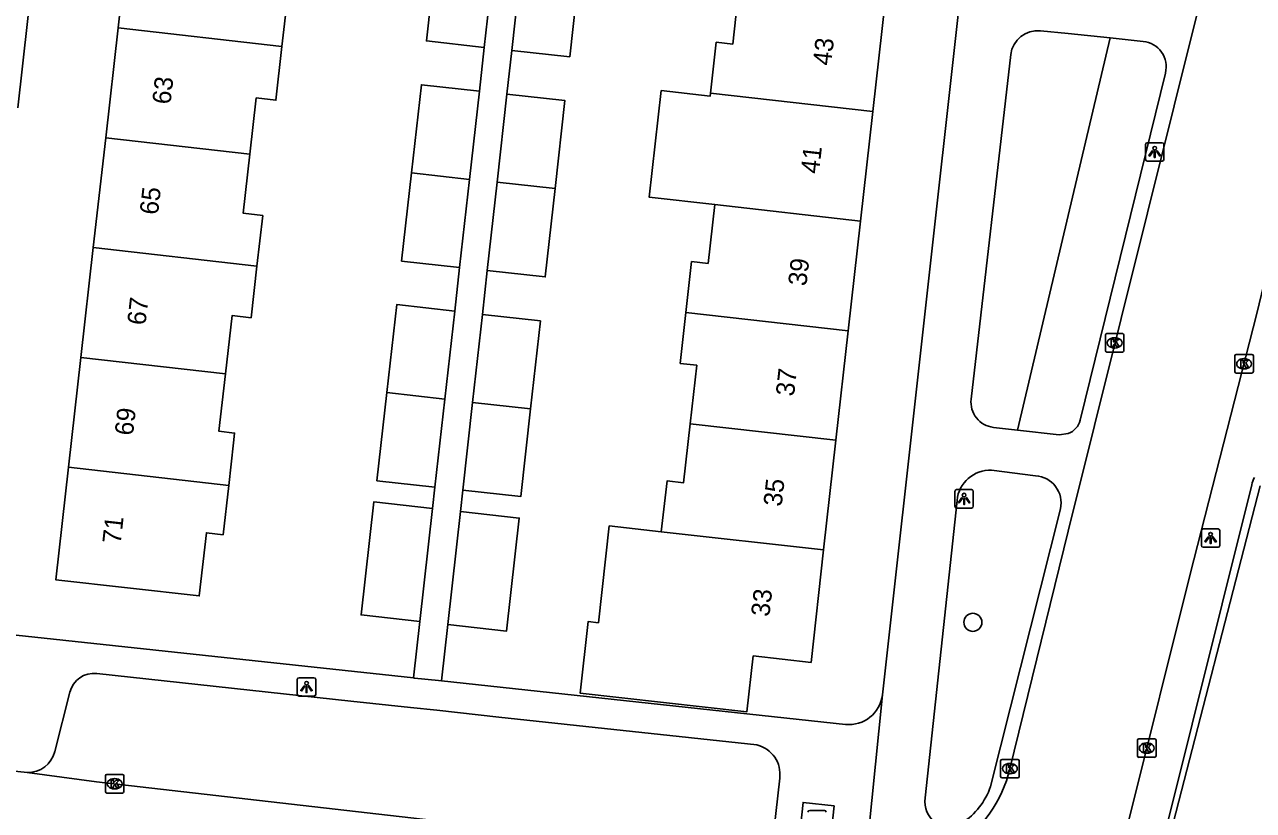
# Model space of a CAD drawing. Extents: x 162026 to 163499, y 387297 to 388169.
# Drawn here: x 162443.5 to 162510, y 387793.2 to 387835.8 of the extents above; entities that cross this region are included whole.
import ezdxf

# ---------------------------------------------------------------- set-up
doc = ezdxf.new("R2010")
doc.units = 0
for name, color, linetype in [('IMGEO_Afval_apart_plaats', 7, 'Continuous'), ('IMGEO_Boom', 7, 'Continuous'), ('IMGEO_Groenvoorziening', 7, 'Continuous'), ('IMGEO_Haag', 7, 'Continuous'), ('IMGEO_Kolk', 7, 'Continuous'), ('IMGEO_Lichtpunt', 7, 'Continuous'), ('IMGEO_Pand', 7, 'Continuous'), ('IMGEO_Pand_nummerreeks', 7, 'Continuous'), ('IMGEO_Rijbaan_lokaal_open', 7, 'Continuous'), ('IMGEO_Voetpad_gesloten', 7, 'Continuous'), ('IMGEO_Voetpad_open', 7, 'Continuous')]:
    doc.layers.add(name, color=color, linetype=linetype)

msp = doc.modelspace()

# ---------------------------------------------------------------- linework, layer by layer
at = {"layer": 'IMGEO_Afval_apart_plaats'}
for p, q in [((162485.995, 387793.2), (162486.785, 387793.2)), ((162486.785, 387793.2), (162485.995, 387793.2))]:
    msp.add_line(p, q, dxfattribs=at)
for centre, start, end in [((162485.995, 387793.1), 90, 180), ((162485.995, 387793.1), 90, 180), ((162486.785, 387793.1), 0, 90), ((162486.785, 387793.1), 360, 90)]:
    msp.add_arc(centre, 0.1, start, end, dxfattribs=at)
at = {"layer": 'IMGEO_Boom'}
msp.add_circle((162494.83, 387803.388), 0.489, dxfattribs=at)
at = {"layer": 'IMGEO_Groenvoorziening'}
msp.add_lwpolyline([(162502.275, 387835.042), (162500, 387825.424), (162497.251, 387813.802)], dxfattribs=at)
at = {"layer": 'IMGEO_Haag'}
msp.add_lwpolyline([(162505.401, 387791.389), (162510.401, 387810.785)], dxfattribs=at)
at = {"layer": 'IMGEO_Kolk'}
for p, q in [((162502.011, 387818.101), (162502.011, 387818.953)), ((162502.086, 387819.027), (162502.938, 387819.027)), ((162502.499, 387818.807), (162502.524, 387818.807)), ((162503.012, 387818.953), (162503.012, 387818.101)), ((162502.938, 387818.027), (162502.086, 387818.027)), ((162502.522, 387818.247), (162502.497, 387818.247)), ((162509.025, 387816.966), (162509.025, 387817.818)), ((162509.1, 387817.892), (162509.952, 387817.892)), ((162510.026, 387817.818), (162510.026, 387816.966)), ((162509.513, 387817.672), (162509.538, 387817.672)), ((162509.952, 387816.892), (162509.1, 387816.892)), ((162509.536, 387817.112), (162509.511, 387817.112)), ((162503.752, 387796.149), (162503.752, 387797.001)), ((162503.827, 387797.075), (162504.679, 387797.075)), ((162504.24, 387796.855), (162504.265, 387796.855)), ((162504.753, 387797.001), (162504.753, 387796.149)), ((162496.336, 387795.036), (162496.336, 387795.888)), ((162496.411, 387795.962), (162497.263, 387795.962)), ((162497.337, 387795.888), (162497.337, 387795.036)), ((162504.679, 387796.075), (162503.827, 387796.075)), ((162504.263, 387796.295), (162504.238, 387796.295)), ((162496.847, 387795.182), (162496.822, 387795.182)), ((162496.824, 387795.742), (162496.849, 387795.742)), ((162447.835, 387794.217), (162447.835, 387795.069)), ((162447.91, 387795.143), (162448.762, 387795.143)), ((162448.323, 387794.923), (162448.348, 387794.923)), ((162448.836, 387795.069), (162448.836, 387794.217)), ((162497.263, 387794.962), (162496.411, 387794.962)), ((162448.762, 387794.143), (162447.91, 387794.143)), ((162448.346, 387794.363), (162448.321, 387794.363))]:
    msp.add_line(p, q, dxfattribs=at)
for points in [[(162502.011, 387818.101), (162502.011, 387818.953)], [(162502.086, 387819.027), (162502.938, 387819.027)], [(162502.332, 387818.727), (162502.455, 387818.727), (162502.455, 387818.576), (162502.585, 387818.727), (162502.749, 387818.727), (162502.603, 387818.576), (162502.756, 387818.327), (162502.604, 387818.327), (162502.519, 387818.491), (162502.455, 387818.424), (162502.455, 387818.327), (162502.332, 387818.327), (162502.332, 387818.727)], [(162503.012, 387818.953), (162503.012, 387818.101)], [(162502.938, 387818.027), (162502.086, 387818.027)], [(162509.025, 387816.966), (162509.025, 387817.818)], [(162509.1, 387817.892), (162509.952, 387817.892)], [(162510.026, 387817.818), (162510.026, 387816.966)], [(162509.346, 387817.592), (162509.469, 387817.592), (162509.469, 387817.441), (162509.599, 387817.592), (162509.763, 387817.592), (162509.617, 387817.441), (162509.77, 387817.192), (162509.618, 387817.192), (162509.533, 387817.356), (162509.469, 387817.289), (162509.469, 387817.192), (162509.346, 387817.192), (162509.346, 387817.592)], [(162509.952, 387816.892), (162509.1, 387816.892)], [(162503.752, 387796.149), (162503.752, 387797.001)], [(162503.827, 387797.075), (162504.679, 387797.075)], [(162504.073, 387796.775), (162504.196, 387796.775), (162504.196, 387796.624), (162504.326, 387796.775), (162504.49, 387796.775), (162504.344, 387796.624), (162504.497, 387796.375), (162504.345, 387796.375), (162504.26, 387796.539), (162504.196, 387796.472), (162504.196, 387796.375), (162504.073, 387796.375), (162504.073, 387796.775)], [(162504.753, 387797.001), (162504.753, 387796.149)], [(162496.336, 387795.036), (162496.336, 387795.888)], [(162496.411, 387795.962), (162497.263, 387795.962)], [(162497.337, 387795.888), (162497.337, 387795.036)], [(162504.679, 387796.075), (162503.827, 387796.075)], [(162496.657, 387795.662), (162496.78, 387795.662), (162496.78, 387795.511), (162496.91, 387795.662), (162497.074, 387795.662), (162496.928, 387795.511), (162497.081, 387795.262), (162496.929, 387795.262), (162496.844, 387795.426), (162496.78, 387795.359), (162496.78, 387795.262), (162496.657, 387795.262), (162496.657, 387795.662)], [(162447.835, 387794.217), (162447.835, 387795.069)], [(162447.91, 387795.143), (162448.762, 387795.143)], [(162448.156, 387794.843), (162448.279, 387794.843), (162448.279, 387794.692), (162448.409, 387794.843), (162448.573, 387794.843), (162448.427, 387794.692), (162448.58, 387794.443), (162448.428, 387794.443), (162448.343, 387794.607), (162448.279, 387794.54), (162448.279, 387794.443), (162448.156, 387794.443), (162448.156, 387794.843)], [(162448.836, 387795.069), (162448.836, 387794.217)], [(162497.263, 387794.962), (162496.411, 387794.962)], [(162448.762, 387794.143), (162447.91, 387794.143)]]:
    msp.add_lwpolyline(points, dxfattribs=at)
for centre, start, end in [((162502.088, 387818.951), 91.55205, 178.44795), ((162502.088, 387818.951), 91.55205, 178.44795), ((162502.936, 387818.951), 1.55205, 88.44795), ((162502.936, 387818.951), 1.55205, 88.44795), ((162502.088, 387818.103), 181.55205, 268.44795), ((162502.088, 387818.103), 181.55205, 268.44795), ((162502.936, 387818.103), 271.55205, 358.44795), ((162502.936, 387818.103), 271.55205, 358.44795), ((162509.102, 387817.816), 91.55205, 178.44795), ((162509.102, 387817.816), 91.55205, 178.44795), ((162509.95, 387817.816), 1.55205, 88.44795), ((162509.95, 387817.816), 1.55205, 88.44795), ((162509.102, 387816.968), 181.55205, 268.44795), ((162509.102, 387816.968), 181.55205, 268.44795), ((162509.95, 387816.968), 271.55205, 358.44795), ((162509.95, 387816.968), 271.55205, 358.44795), ((162503.829, 387796.999), 91.55205, 178.44795), ((162503.829, 387796.999), 91.55205, 178.44795), ((162504.677, 387796.999), 1.55205, 88.44795), ((162504.677, 387796.999), 1.55205, 88.44795), ((162496.413, 387795.886), 91.55205, 178.44795), ((162496.413, 387795.886), 91.55205, 178.44795), ((162497.261, 387795.886), 1.55205, 88.44795), ((162497.261, 387795.886), 1.55205, 88.44795), ((162503.829, 387796.151), 181.55205, 268.44795), ((162503.829, 387796.151), 181.55205, 268.44795), ((162504.677, 387796.151), 271.55205, 358.44795), ((162504.677, 387796.151), 271.55205, 358.44795), ((162447.912, 387795.067), 91.55205, 178.44795), ((162447.912, 387795.067), 91.55205, 178.44795), ((162448.76, 387795.067), 1.55205, 88.44795), ((162448.76, 387795.067), 1.55205, 88.44795), ((162496.413, 387795.038), 181.55205, 268.44795), ((162496.413, 387795.038), 181.55205, 268.44795), ((162497.261, 387795.038), 271.55205, 358.44795), ((162497.261, 387795.038), 271.55205, 358.44795), ((162447.912, 387794.219), 181.55205, 268.44795), ((162447.912, 387794.219), 181.55205, 268.44795), ((162448.76, 387794.219), 271.55205, 358.44795), ((162448.76, 387794.219), 271.55205, 358.44795)]:
    msp.add_arc(centre, 0.0765, start, end, dxfattribs=at)
for centre, major_axis, ratio, start_param, end_param in [((162502.498, 387818.527), (-0.387, 0.002), 0.722429, 4.712389, 7.853982), ((162502.523, 387818.527), (-0.39, 0.002), 0.717154, 1.570796, 4.712389), ((162509.512, 387817.392), (-0.387, 0.002), 0.722429, 4.712389, 7.853982), ((162509.537, 387817.392), (-0.39, 0.002), 0.717154, 1.570796, 4.712389), ((162504.239, 387796.575), (-0.387, 0.002), 0.722429, 4.712389, 7.853982), ((162504.264, 387796.575), (-0.39, 0.002), 0.717154, 1.570796, 4.712389), ((162496.823, 387795.462), (-0.387, 0.002), 0.722429, 4.712389, 7.853982), ((162496.848, 387795.462), (-0.39, 0.002), 0.717154, 1.570796, 4.712389), ((162448.322, 387794.643), (-0.387, 0.002), 0.722429, 4.712389, 7.853982), ((162448.347, 387794.643), (-0.39, 0.002), 0.717154, 1.570796, 4.712389)]:
    msp.add_ellipse(centre, major_axis=major_axis, ratio=ratio, start_param=start_param, end_param=end_param, dxfattribs=at)
at = {"layer": 'IMGEO_Lichtpunt'}
for p, q in [((162504.186, 387829.273), (162504.186, 387828.466)), ((162504.186, 387829.273), (162504.186, 387828.466)), ((162505.088, 387829.368), (162504.28, 387829.368)), ((162505.088, 387829.368), (162504.28, 387829.368)), ((162505.182, 387828.466), (162505.182, 387829.273)), ((162505.182, 387828.466), (162505.182, 387829.273)), ((162504.28, 387828.372), (162505.088, 387828.372)), ((162504.28, 387828.372), (162505.088, 387828.372)), ((162494.76, 387810.575), (162493.952, 387810.575)), ((162494.76, 387810.575), (162493.952, 387810.575)), ((162493.858, 387810.48), (162493.858, 387809.673)), ((162493.858, 387810.48), (162493.858, 387809.673)), ((162494.854, 387809.673), (162494.854, 387810.48)), ((162494.854, 387809.673), (162494.854, 387810.48)), ((162493.952, 387809.579), (162494.76, 387809.579)), ((162493.952, 387809.579), (162494.76, 387809.579)), ((162507.213, 387808.358), (162507.213, 387807.551)), ((162507.213, 387808.358), (162507.213, 387807.551)), ((162508.115, 387808.453), (162507.307, 387808.453)), ((162508.115, 387808.453), (162507.307, 387808.453)), ((162508.209, 387807.551), (162508.209, 387808.358)), ((162508.209, 387807.551), (162508.209, 387808.358)), ((162507.307, 387807.457), (162508.115, 387807.457)), ((162507.307, 387807.457), (162508.115, 387807.457)), ((162458.232, 387800.29), (162458.232, 387799.483)), ((162458.232, 387800.29), (162458.232, 387799.483)), ((162459.134, 387800.385), (162458.326, 387800.385)), ((162459.134, 387800.385), (162458.326, 387800.385)), ((162459.228, 387799.483), (162459.228, 387800.29)), ((162459.228, 387799.483), (162459.228, 387800.29)), ((162458.326, 387799.389), (162459.134, 387799.389)), ((162458.326, 387799.389), (162459.134, 387799.389))]:
    msp.add_line(p, q, dxfattribs=at)
for points in [[(162504.56, 387828.937), (162504.599, 387828.909), (162504.411, 387828.647), (162504.373, 387828.674), (162504.56, 387828.937)], [(162504.662, 387828.889), (162504.709, 387828.889), (162504.709, 387828.567), (162504.662, 387828.567), (162504.662, 387828.889)], [(162504.772, 387828.909), (162504.81, 387828.936), (162504.997, 387828.674), (162504.958, 387828.646), (162504.772, 387828.909)], [(162494.232, 387810.144), (162494.271, 387810.116), (162494.083, 387809.854), (162494.045, 387809.881), (162494.232, 387810.144)], [(162494.334, 387810.096), (162494.381, 387810.096), (162494.381, 387809.774), (162494.334, 387809.774), (162494.334, 387810.096)], [(162494.444, 387810.116), (162494.482, 387810.143), (162494.669, 387809.881), (162494.63, 387809.853), (162494.444, 387810.116)], [(162507.587, 387808.022), (162507.626, 387807.994), (162507.438, 387807.732), (162507.4, 387807.759), (162507.587, 387808.022)], [(162507.689, 387807.974), (162507.736, 387807.974), (162507.736, 387807.652), (162507.689, 387807.652), (162507.689, 387807.974)], [(162507.799, 387807.994), (162507.837, 387808.021), (162508.024, 387807.759), (162507.985, 387807.731), (162507.799, 387807.994)], [(162458.606, 387799.954), (162458.645, 387799.926), (162458.457, 387799.664), (162458.419, 387799.691), (162458.606, 387799.954)], [(162458.708, 387799.906), (162458.755, 387799.906), (162458.755, 387799.584), (162458.708, 387799.584), (162458.708, 387799.906)], [(162458.818, 387799.926), (162458.856, 387799.953), (162459.043, 387799.691), (162459.004, 387799.663), (162458.818, 387799.926)]]:
    msp.add_lwpolyline(points, dxfattribs=at)
for centre in [(162504.685, 387829.071), (162494.357, 387810.278), (162507.712, 387808.156), (162458.731, 387800.088)]:
    msp.add_circle(centre, 0.0994, dxfattribs=at)
for centre, start, end in [((162504.28, 387829.273), 90, 180), ((162504.28, 387829.273), 90, 180), ((162505.088, 387829.273), 0, 90), ((162505.088, 387829.273), 0, 90), ((162504.28, 387828.466), 180, 270), ((162504.28, 387828.466), 180, 270), ((162505.088, 387828.466), 270, 0), ((162505.088, 387828.466), 270, 360), ((162493.952, 387810.48), 90, 180), ((162493.952, 387810.48), 90, 180), ((162494.76, 387810.48), 0, 90), ((162494.76, 387810.48), 0, 90), ((162493.952, 387809.673), 180, 270), ((162493.952, 387809.673), 180, 270), ((162494.76, 387809.673), 270, 0), ((162494.76, 387809.673), 270, 360), ((162507.307, 387808.358), 90, 180), ((162507.307, 387808.358), 90, 180), ((162508.115, 387808.358), 0, 90), ((162508.115, 387808.358), 0, 90), ((162507.307, 387807.551), 180, 270), ((162507.307, 387807.551), 180, 270), ((162508.115, 387807.551), 270, 0), ((162508.115, 387807.551), 270, 360), ((162458.326, 387800.29), 90, 180), ((162458.326, 387800.29), 90, 180), ((162459.134, 387800.29), 0, 90), ((162459.134, 387800.29), 0, 90), ((162458.326, 387799.483), 180, 270), ((162458.326, 387799.483), 180, 270), ((162459.134, 387799.483), 270, 0), ((162459.134, 387799.483), 270, 360)]:
    msp.add_arc(centre, 0.0946, start, end, dxfattribs=at)
at = {"layer": 'IMGEO_Pand'}
for points in [[(162448.529, 387835.59), (162449.203, 387841.54)], [(162457.037, 387840.652), (162456.661, 387837.333), (162457.7, 387837.215), (162457.402, 387834.584)], [(162468.363, 387834.533), (162465.222, 387834.885), (162465.758, 387839.658)], [(162468.363, 387834.533), (162468.899, 387839.305)], [(162470.381, 387839.145), (162469.85, 387834.369)], [(162473.522, 387838.795), (162472.991, 387834.02), (162469.85, 387834.369)], [(162480.617, 387832.05), (162480.928, 387834.81), (162481.82, 387834.709), (162482.177, 387837.891)], [(162490.075, 387837.005), (162489.409, 387831.065)], [(162447.855, 387829.64), (162448.529, 387835.59)], [(162448.529, 387835.59), (162457.402, 387834.584)], [(162457.402, 387834.584), (162457.072, 387831.671), (162456.007, 387831.792), (162455.663, 387828.755)], [(162464.419, 387827.735), (162464.955, 387832.505), (162468.095, 387832.153)], [(162467.56, 387827.383), (162468.095, 387832.153)], [(162469.586, 387831.998), (162469.056, 387827.227)], [(162469.586, 387831.998), (162472.727, 387831.648), (162472.196, 387826.878)], [(162480.845, 387826.012), (162477.298, 387826.41), (162477.947, 387832.187), (162480.599, 387831.889), (162480.617, 387832.05)], [(162489.409, 387831.065), (162480.617, 387832.05)], [(162489.409, 387831.065), (162488.743, 387825.126)], [(162447.18, 387823.69), (162447.855, 387829.64)], [(162447.855, 387829.64), (162455.663, 387828.755)], [(162455.663, 387828.755), (162455.299, 387825.542), (162456.357, 387825.422), (162456.047, 387822.685)], [(162464.419, 387827.735), (162463.883, 387822.956), (162467.023, 387822.603)], [(162467.56, 387827.383), (162464.419, 387827.735)], [(162467.023, 387822.603), (162467.56, 387827.383)], [(162469.056, 387827.227), (162468.524, 387822.451)], [(162469.056, 387827.227), (162472.196, 387826.878)], [(162472.196, 387826.878), (162471.665, 387822.102), (162468.524, 387822.451)], [(162479.285, 387820.171), (162479.596, 387822.931), (162480.488, 387822.83), (162480.845, 387826.012)], [(162480.845, 387826.012), (162488.743, 387825.126)], [(162488.743, 387825.126), (162488.077, 387819.186)], [(162446.506, 387817.74), (162447.18, 387823.69)], [(162456.047, 387822.685), (162447.18, 387823.69)], [(162456.047, 387822.685), (162455.73, 387819.886), (162454.7, 387820.003), (162454.343, 387816.852)], [(162463.082, 387815.83), (162463.618, 387820.6), (162466.758, 387820.248)], [(162466.223, 387815.478), (162466.758, 387820.248)], [(162468.259, 387820.065), (162467.729, 387815.304)], [(162468.259, 387820.065), (162471.4, 387819.715), (162470.87, 387814.955)], [(162479.513, 387814.132), (162479.87, 387817.312), (162478.974, 387817.413), (162479.285, 387820.171)], [(162488.077, 387819.186), (162479.285, 387820.171)], [(162488.077, 387819.186), (162487.411, 387813.246)], [(162445.832, 387811.79), (162446.506, 387817.74)], [(162446.506, 387817.74), (162454.343, 387816.852)], [(162454.343, 387816.852), (162453.989, 387813.734), (162454.836, 387813.638), (162454.775, 387813.102), (162454.513, 387810.806)], [(162465.686, 387810.703), (162462.546, 387811.056), (162463.082, 387815.83)], [(162466.223, 387815.478), (162463.082, 387815.83)], [(162465.686, 387810.703), (162466.223, 387815.478)], [(162467.729, 387815.304), (162467.2, 387810.546)], [(162467.729, 387815.304), (162470.87, 387814.955)], [(162470.87, 387814.955), (162470.341, 387810.196), (162467.2, 387810.546)], [(162477.953, 387808.291), (162478.264, 387811.051), (162479.156, 387810.95), (162479.513, 387814.132)], [(162479.513, 387814.132), (162487.411, 387813.246)], [(162487.411, 387813.246), (162486.746, 387807.306)], [(162454.513, 387810.806), (162454.208, 387808.134), (162453.303, 387808.237), (162452.915, 387804.814), (162445.141, 387805.695), (162445.832, 387811.79)], [(162454.513, 387810.806), (162445.832, 387811.79)], [(162464.87, 387803.434), (162461.69, 387803.791), (162462.377, 387809.91), (162465.557, 387809.553)], [(162464.87, 387803.434), (162465.557, 387809.553)], [(162467.071, 387809.388), (162466.39, 387803.264)], [(162466.39, 387803.264), (162469.571, 387802.91), (162470.252, 387809.034), (162467.071, 387809.388)], [(162486.746, 387807.306), (162486.063, 387801.218), (162482.933, 387801.57), (162482.593, 387798.54), (162473.55, 387799.555), (162473.985, 387803.431), (162474.549, 387803.368), (162475.136, 387808.607), (162477.953, 387808.291)], [(162486.746, 387807.306), (162477.953, 387808.291)]]:
    msp.add_lwpolyline(points, dxfattribs=at)
at = {"layer": 'IMGEO_Rijbaan_lokaal_open'}
for points in [[(162496.838, 387795.458), (162500, 387808.321), (162507.158, 387837.115), (162508.491, 387842.477)], [(162515.142, 387840.09), (162513.415, 387833.351), (162510.223, 387820.11), (162506.595, 387805.998), (162500, 387779.488), (162496.122, 387762.552)], [(162485.508, 387790.382), (162447.347, 387794.755), (162443.597, 387795.248)]]:
    msp.add_lwpolyline(points, dxfattribs=at)
for centre, radius, start, end in [((162452.524, 387863.991), 69.321, 255.76268, 262.60131), ((162489.798, 387797.186), 7.249, 263.44693, 346.20503)]:
    msp.add_arc(centre, radius, start, end, dxfattribs=at)
at = {"layer": 'IMGEO_Voetpad_gesloten'}
msp.add_lwpolyline([(162487.325, 387793.455), (162487.144, 387791.764), (162485.455, 387791.945), (162485.636, 387793.636), (162487.325, 387793.455)], dxfattribs=at)
at = {"layer": 'IMGEO_Voetpad_open'}
for points in [[(162489.932, 387799.465), (162494.267, 387838.446), (162500, 387890.005), (162501.72, 387906.704)], [(162451.123, 387903.043), (162443.098, 387831.258)], [(162498.494, 387835.432), (162500, 387835.277), (162502.275, 387835.042)], [(162468.095, 387832.153), (162468.363, 387834.533)], [(162502.275, 387835.042), (162504.059, 387834.857)], [(162469.85, 387834.369), (162469.586, 387831.998)], [(162494.735, 387815.467), (162496.882, 387834.142)], [(162505.266, 387833.143), (162500.647, 387814.34)], [(162466.758, 387820.248), (162467.023, 387822.603)], [(162468.524, 387822.451), (162468.259, 387820.065)], [(162497.251, 387813.802), (162495.945, 387813.948)], [(162500.001, 387813.611), (162499.512, 387813.548), (162497.251, 387813.802)], [(162495.849, 387811.634), (162498.231, 387811.325)], [(162465.557, 387809.553), (162465.686, 387810.703)], [(162467.2, 387810.546), (162467.071, 387809.388)], [(162509.941, 387810.841), (162505.107, 387791.423)], [(162492.252, 387793.874), (162493.974, 387809.994)], [(162499.576, 387809.541), (162495.79, 387794.493)], [(162464.526, 387800.374), (162464.87, 387803.434)], [(162466.39, 387803.264), (162466.051, 387800.21)], [(162441.802, 387802.814), (162464.526, 387800.374)], [(162447.364, 387800.612), (162461.127, 387799.125), (162464.371, 387798.774), (162465.791, 387798.621), (162469.157, 387798.257), (162483.133, 387796.747)], [(162466.051, 387800.21), (162465.885, 387800.228), (162464.579, 387800.368), (162464.526, 387800.374)], [(162466.051, 387800.21), (162487.924, 387797.861)], [(162445.094, 387796.389), (162445.915, 387799.603)], [(162488.971, 387789.985), (162489.932, 387799.465)], [(162484.365, 387794.942), (162484.048, 387792.074)]]:
    msp.add_lwpolyline(points, dxfattribs=at)
for centre, radius, start, end in [((162498.344, 387833.968), 1.472, 84.14208, 173.19487), ((162503.917, 387833.475), 1.389, 346.15909, 84.14738), ((162496.099, 387815.312), 1.373, 173.51434, 263.56568), ((162499.63, 387814.591), 1.048, 290.75224, 346.15654), ((162495.78, 387809.821), 1.815, 87.83259, 174.51763), ((162498.142, 387809.859), 1.468, 347.4842, 86.54281), ((162511.825, 387810.378), 1.94, 153.95343, 166.19866), ((162447.212, 387799.285), 1.336, 83.48464, 166.21761), ((162488.118, 387799.677), 1.826, 263.89349, 353.34256), ((162482.751, 387795.163), 1.629, 352.18634, 76.44453), ((162443.631, 387796.756), 1.508, 268.70044, 345.92821), ((162493.574, 387793.643), 1.342, 170.07894, 235.71829), ((162492.068, 387795.804), 3.946, 303.51827, 340.59559)]:
    msp.add_arc(centre, radius, start, end, dxfattribs=at)

# ---------------------------------------------------------------- texts
at = {"layer": 'IMGEO_Pand_nummerreeks'}
for s, rotation, p in [('43', 83.60314, (162487.147, 387833.513)), ('63', 83.53458, (162451.357, 387831.411)), ('41', 83.606, (162486.491, 387827.655)), ('65', 83.53458, (162450.679, 387825.432)), ('39', 83.60314, (162485.809, 387821.573)), ('67', 83.53458, (162450.002, 387819.453)), ('37', 83.60314, (162485.139, 387815.603)), ('69', 83.53458, (162449.324, 387813.473)), ('35', 83.60314, (162484.47, 387809.633)), ('71', 83.53458, (162448.658, 387807.607)), ('33', 83.60314, (162483.801, 387803.663))]:
    msp.add_text(s, height=1, rotation=rotation, dxfattribs=at).set_placement(p)

doc.saveas('drawing.dxf')
